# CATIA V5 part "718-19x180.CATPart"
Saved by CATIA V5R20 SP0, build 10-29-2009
Part number: 718-19x180
Definition: NONE
Nomenclature: 718-19x180
Source: Unknown
Description: 718-19x180
Bounding box of the stored display mesh (mm): x 0 to 203, y -12.5 to 12.5, z -12.5 to 12.5
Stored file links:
  C:\Users\Utente\Desktop\IO LAVORO\3D X SITO CF\X SITO\718\718-19x180.CATPart

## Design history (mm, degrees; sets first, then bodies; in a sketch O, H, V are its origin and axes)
Body1 "718-19x180" (main body)
  Solid1: solid without history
